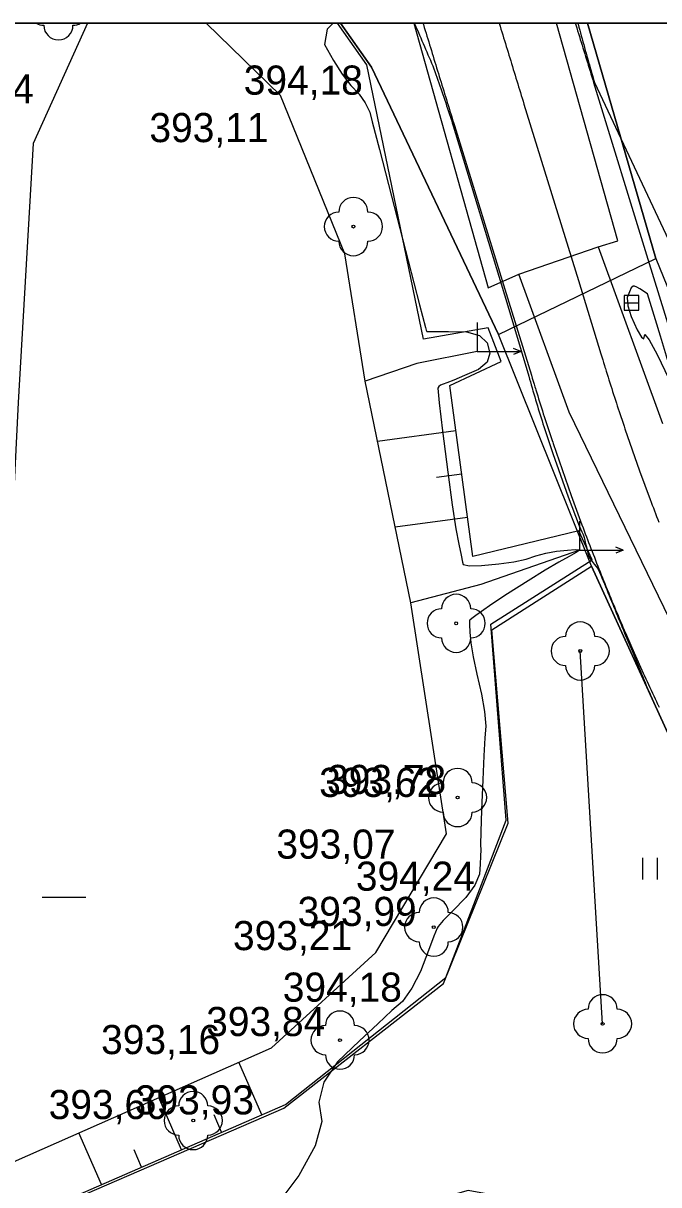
# Model space of a CAD drawing. Extents: x -574342 to -508101, y -1143544 to -1123894.
# Drawn here: x -508495.78 to -508473.95, y -1143155.94 to -1143116.06 of the extents above; entities that cross this region are included whole.
import ezdxf

# ---------------------------------------------------------------- set-up
doc = ezdxf.new("R2010")
doc.units = 0
for name, color, linetype in [('01_PARCELY_NAVRH_PC', 7, 'Continuous'), ('01_PARCELY_NAVRH_VHO', 7, 'Continuous'), ('01_PARCELY_NAVRH_ŽP', 7, 'Continuous'), ('1000', 7, 'Continuous'), ('21', 7, 'Continuous'), ('30', 7, 'Continuous'), ('37', 7, 'Continuous'), ('43', 7, 'Continuous'), ('51', 7, 'Continuous'), ('52', 7, 'Continuous'), ('54', 7, 'Continuous'), ('55', 7, 'Continuous'), ('60', 7, 'Continuous'), ('61', 7, 'Continuous'), ('Level 1', 7, 'Continuous'), ('Level 255', 7, 'Continuous'), ('VRST VEDL', 7, 'Continuous')]:
    doc.layers.add(name, color=color, linetype=linetype)

msp = doc.modelspace()

# ---------------------------------------------------------------- linework, layer by layer
at = {"layer": '01_PARCELY_NAVRH_PC'}
msp.add_line((-508476.398, -1143116.058), (-508484.878, -1143116.058), dxfattribs=at)
for points in [[(-508484.878, -1143116.058), (-508483.82, -1143117.57), (-508479.46, -1143126.74), (-508474.05, -1143124.14), (-508476.398, -1143116.058)], [(-508445.99, -1143206.42), (-508454.33, -1143183.49), (-508456.87, -1143173.84), (-508463.3, -1143163.03), (-508476.26, -1143134.7), (-508479.46, -1143126.74), (-508474.05, -1143124.14), (-508467.92, -1143139.18), (-508459.97, -1143152.33), (-508456.09, -1143158.71), (-508451.57, -1143168.14), (-508437.66, -1143207.58)]]:
    msp.add_lwpolyline(points, dxfattribs=at)
at = {"layer": '01_PARCELY_NAVRH_VHO'}
msp.add_line((-508484.878, -1143116.058), (-508496.906, -1143116.058), dxfattribs=at)
msp.add_lwpolyline([(-508497.89, -1143158.09), (-508486.83, -1143153.3), (-508481.34, -1143149.03), (-508479.12, -1143143.52), (-508479.68, -1143136.88), (-508476.26, -1143134.7), (-508479.46, -1143126.74), (-508483.82, -1143117.57), (-508484.878, -1143116.058)], dxfattribs=at)
at = {"layer": '01_PARCELY_NAVRH_ŽP'}
msp.add_line((-508467.879, -1143116.058), (-508476.398, -1143116.058), dxfattribs=at)
msp.add_lwpolyline([(-508476.398, -1143116.058), (-508474.05, -1143124.14), (-508467.92, -1143139.18), (-508459.97, -1143152.33), (-508456.09, -1143158.71), (-508451.57, -1143168.14), (-508437.66, -1143207.58), (-508425.52, -1143241.92), (-508422.7, -1143249.88), (-508420.04, -1143252.1), (-508417.38, -1143252.95), (-508415.56, -1143252.78), (-508448.24, -1143160.16), (-508453.75, -1143145.01), (-508465.11, -1143123.03), (-508467.879, -1143116.058)], dxfattribs=at)
msp.add_lwpolyline([(-508521.06, -1143176.58), (-508518.2, -1143171.1), (-508515.68, -1143172.08), (-508512.27, -1143171.56), (-508509.12, -1143169.33), (-508497.89, -1143158.09), (-508486.83, -1143153.3), (-508481.34, -1143149.03), (-508479.12, -1143143.52), (-508479.68, -1143136.88), (-508476.26, -1143134.7), (-508463.3, -1143163.03), (-508471.45, -1143157.79), (-508480.5, -1143156.13), (-508491.25, -1143159.19), (-508499.36, -1143164.43), (-508507.52, -1143173.92), (-508509.38, -1143179.27), (-508513.26, -1143177.6)], close=True, dxfattribs=at)
at = {"layer": '1000'}
for points in [[(-508482.347, -1143116.058), (-508482.334, -1143116.087), (-508482.292, -1143116.182), (-508482.25, -1143116.278), (-508482.208, -1143116.373), (-508482.167, -1143116.469), (-508482.125, -1143116.564), (-508482.084, -1143116.66), (-508482.042, -1143116.756), (-508482.001, -1143116.851), (-508481.96, -1143116.947), (-508481.919, -1143117.043), (-508481.878, -1143117.138), (-508481.837, -1143117.234), (-508481.797, -1143117.33), (-508481.756, -1143117.426), (-508481.715, -1143117.522), (-508481.675, -1143117.618), (-508481.639, -1143117.715), (-508481.605, -1143117.813), (-508481.571, -1143117.911), (-508481.537, -1143118.009), (-508481.504, -1143118.107), (-508481.47, -1143118.205), (-508481.436, -1143118.303), (-508481.403, -1143118.401), (-508481.37, -1143118.499), (-508481.336, -1143118.597), (-508481.303, -1143118.695), (-508481.27, -1143118.793), (-508481.237, -1143118.891), (-508481.205, -1143118.99), (-508481.172, -1143119.088), (-508481.139, -1143119.186), (-508481.107, -1143119.285), (-508481.075, -1143119.383), (-508481.042, -1143119.482), (-508481.01, -1143119.58), (-508479.166, -1143125.649)], [(-508482.052, -1143116.058), (-508482.037, -1143116.104), (-508482.007, -1143116.203), (-508481.976, -1143116.302), (-508481.946, -1143116.401), (-508481.915, -1143116.5), (-508481.885, -1143116.599), (-508481.854, -1143116.698), (-508481.824, -1143116.797), (-508481.793, -1143116.896), (-508481.763, -1143116.995), (-508481.732, -1143117.094), (-508481.702, -1143117.192), (-508481.672, -1143117.291), (-508481.641, -1143117.39), (-508481.611, -1143117.489), (-508481.58, -1143117.588), (-508481.55, -1143117.687), (-508481.519, -1143117.786), (-508481.489, -1143117.885), (-508481.458, -1143117.984), (-508481.428, -1143118.083), (-508481.397, -1143118.182), (-508481.367, -1143118.281), (-508481.336, -1143118.38), (-508481.306, -1143118.479), (-508481.275, -1143118.578), (-508481.245, -1143118.677), (-508481.214, -1143118.776), (-508481.184, -1143118.875), (-508481.153, -1143118.974), (-508481.123, -1143119.073), (-508481.092, -1143119.172), (-508481.062, -1143119.271), (-508481.031, -1143119.37), (-508481.001, -1143119.469), (-508480.97, -1143119.568), (-508479.103, -1143125.63)], [(-508476.82, -1143116.058), (-508476.802, -1143116.116), (-508476.771, -1143116.215), (-508476.741, -1143116.314), (-508476.71, -1143116.413), (-508476.68, -1143116.512), (-508476.649, -1143116.611), (-508476.619, -1143116.71), (-508476.588, -1143116.809), (-508476.558, -1143116.908), (-508476.527, -1143117.007), (-508476.497, -1143117.106), (-508476.466, -1143117.205), (-508476.436, -1143117.304), (-508476.405, -1143117.403), (-508476.375, -1143117.502), (-508476.344, -1143117.601), (-508476.314, -1143117.7), (-508476.283, -1143117.799), (-508476.253, -1143117.898), (-508476.222, -1143117.997), (-508476.192, -1143118.096), (-508474.325, -1143124.158)], [(-508476.731, -1143116.058), (-508476.722, -1143116.092), (-508476.694, -1143116.192), (-508476.667, -1143116.292), (-508476.64, -1143116.392), (-508476.613, -1143116.492), (-508476.585, -1143116.592), (-508476.558, -1143116.691), (-508476.53, -1143116.791), (-508476.502, -1143116.891), (-508476.475, -1143116.991), (-508476.447, -1143117.091), (-508476.419, -1143117.19), (-508476.391, -1143117.29), (-508476.362, -1143117.39), (-508476.334, -1143117.489), (-508476.306, -1143117.589), (-508476.277, -1143117.689), (-508476.249, -1143117.788), (-508476.22, -1143117.888), (-508476.192, -1143117.987), (-508476.163, -1143118.087), (-508473.44, -1143123.887)], [(-508474.325, -1143124.158), (-508473.55, -1143126.674)], [(-508479.166, -1143125.649), (-508478.416, -1143128.173), (-508478.388, -1143128.273), (-508478.359, -1143128.373), (-508478.331, -1143128.473), (-508478.302, -1143128.573), (-508478.286, -1143128.63), (-508478.273, -1143128.675), (-508478.243, -1143128.778), (-508478.213, -1143128.881), (-508478.182, -1143128.984), (-508478.152, -1143129.087), (-508478.121, -1143129.19), (-508478.09, -1143129.293), (-508478.058, -1143129.395), (-508478.026, -1143129.498), (-508477.995, -1143129.601), (-508477.962, -1143129.703), (-508477.93, -1143129.806), (-508477.897, -1143129.908), (-508477.864, -1143130.01), (-508477.831, -1143130.112), (-508477.798, -1143130.215), (-508477.764, -1143130.317), (-508477.73, -1143130.419), (-508477.709, -1143130.482), (-508477.696, -1143130.52), (-508477.662, -1143130.622), (-508477.627, -1143130.724), (-508477.593, -1143130.826), (-508477.065, -1143132.312), (-508476.682, -1143133.316), (-508476.638, -1143133.416), (-508476.595, -1143133.515), (-508476.552, -1143133.614), (-508476.513, -1143133.715), (-508476.488, -1143133.822), (-508476.464, -1143133.928), (-508476.439, -1143134.034), (-508476.414, -1143134.14), (-508476.414, -1143134.14), (-508476.388, -1143134.247), (-508476.363, -1143134.353), (-508476.314, -1143134.45), (-508476.242, -1143134.538), (-508476.169, -1143134.626), (-508476.097, -1143134.713), (-508476.035, -1143134.805), (-508475.99, -1143134.903), (-508475.947, -1143135.002), (-508475.905, -1143135.102), (-508475.863, -1143135.201), (-508475.821, -1143135.3), (-508475.821, -1143135.301), (-508475.78, -1143135.401), (-508475.739, -1143135.501), (-508475.698, -1143135.601), (-508475.658, -1143135.701), (-508475.617, -1143135.801), (-508475.579, -1143135.894), (-508475.576, -1143135.901), (-508475.535, -1143136.001), (-508475.494, -1143136.101), (-508475.453, -1143136.201), (-508475.412, -1143136.301), (-508475.371, -1143136.401), (-508475.33, -1143136.501), (-508475.289, -1143136.601), (-508475.247, -1143136.701), (-508475.206, -1143136.801), (-508475.165, -1143136.9), (-508475.124, -1143137), (-508474.837, -1143137.685), (-508474.542, -1143138.392), (-508474.502, -1143138.492), (-508474.461, -1143138.593), (-508474.421, -1143138.693), (-508474.38, -1143138.793), (-508474.339, -1143138.893), (-508474.296, -1143138.992), (-508474.252, -1143139.091), (-508474.208, -1143139.19), (-508474.164, -1143139.289), (-508474.12, -1143139.387), (-508474.082, -1143139.471), (-508474.075, -1143139.486), (-508474.03, -1143139.584), (-508473.985, -1143139.682), (-508473.94, -1143139.78)], [(-508479.103, -1143125.63), (-508478.328, -1143128.146), (-508478.297, -1143128.245), (-508478.267, -1143128.344), (-508478.236, -1143128.444), (-508478.206, -1143128.543), (-508478.188, -1143128.599), (-508478.174, -1143128.644), (-508478.143, -1143128.747), (-508478.111, -1143128.849), (-508478.079, -1143128.951), (-508478.047, -1143129.054), (-508478.015, -1143129.156), (-508477.982, -1143129.258), (-508477.95, -1143129.361), (-508477.917, -1143129.463), (-508477.884, -1143129.565), (-508477.851, -1143129.667), (-508477.818, -1143129.769), (-508477.785, -1143129.871), (-508477.752, -1143129.973), (-508477.718, -1143130.075), (-508477.685, -1143130.177), (-508477.651, -1143130.279), (-508477.617, -1143130.381), (-508477.596, -1143130.444), (-508477.583, -1143130.483), (-508477.549, -1143130.584), (-508477.515, -1143130.686), (-508477.481, -1143130.788), (-508476.961, -1143132.274), (-508476.591, -1143133.282), (-508476.553, -1143133.383), (-508476.514, -1143133.485), (-508476.476, -1143133.586), (-508476.438, -1143133.686), (-508476.399, -1143133.787), (-508476.361, -1143133.888), (-508476.322, -1143133.989), (-508476.283, -1143134.089), (-508476.283, -1143134.09), (-508476.244, -1143134.191), (-508476.205, -1143134.291), (-508476.165, -1143134.392), (-508476.126, -1143134.492), (-508476.086, -1143134.593), (-508476.047, -1143134.693), (-508476.007, -1143134.794), (-508475.967, -1143134.894), (-508475.927, -1143134.994), (-508475.886, -1143135.095), (-508475.846, -1143135.195), (-508475.806, -1143135.294), (-508475.806, -1143135.295), (-508475.765, -1143135.395), (-508475.724, -1143135.495), (-508475.683, -1143135.595), (-508475.642, -1143135.695), (-508475.601, -1143135.795), (-508475.563, -1143135.887), (-508475.56, -1143135.895), (-508475.518, -1143135.994), (-508475.477, -1143136.094), (-508475.435, -1143136.194), (-508475.393, -1143136.293), (-508475.351, -1143136.393), (-508475.309, -1143136.492), (-508475.267, -1143136.592), (-508475.225, -1143136.691), (-508475.182, -1143136.79), (-508475.14, -1143136.89), (-508475.097, -1143136.989), (-508474.8, -1143137.668), (-508474.487, -1143138.367), (-508474.443, -1143138.466), (-508474.398, -1143138.564), (-508474.353, -1143138.662), (-508474.308, -1143138.76), (-508474.263, -1143138.858), (-508474.218, -1143138.956), (-508474.172, -1143139.054), (-508474.127, -1143139.152), (-508474.081, -1143139.25), (-508474.035, -1143139.348), (-508473.996, -1143139.431), (-508473.99, -1143139.445), (-508473.944, -1143139.543)]]:
    msp.add_lwpolyline(points, dxfattribs=at)
at = {"layer": '21'}
for points in [[(-508479.436, -1143116.058), (-508479.435, -1143116.061), (-508479.404, -1143116.16), (-508479.374, -1143116.259), (-508479.343, -1143116.358), (-508479.313, -1143116.457), (-508479.282, -1143116.555), (-508479.252, -1143116.654), (-508479.221, -1143116.753), (-508479.191, -1143116.852), (-508479.16, -1143116.951), (-508479.13, -1143117.05), (-508479.099, -1143117.149), (-508479.069, -1143117.248), (-508479.038, -1143117.347), (-508479.008, -1143117.446), (-508478.977, -1143117.545), (-508478.947, -1143117.644), (-508478.916, -1143117.743), (-508478.886, -1143117.842), (-508478.856, -1143117.941), (-508478.825, -1143118.04), (-508478.795, -1143118.139), (-508478.764, -1143118.238), (-508478.734, -1143118.337), (-508478.703, -1143118.436), (-508478.673, -1143118.535), (-508478.642, -1143118.634), (-508478.612, -1143118.733), (-508478.581, -1143118.832), (-508476.714, -1143124.894)], [(-508476.714, -1143124.894), (-508475.939, -1143127.41), (-508475.908, -1143127.509), (-508475.878, -1143127.609), (-508475.847, -1143127.708), (-508475.816, -1143127.807), (-508475.799, -1143127.863), (-508475.786, -1143127.907), (-508475.755, -1143128.006), (-508475.724, -1143128.106), (-508475.693, -1143128.205), (-508475.662, -1143128.304), (-508475.631, -1143128.403), (-508475.599, -1143128.503), (-508475.568, -1143128.602), (-508475.536, -1143128.701), (-508475.504, -1143128.8), (-508475.472, -1143128.899), (-508475.44, -1143128.998), (-508475.408, -1143129.097), (-508475.376, -1143129.196), (-508475.343, -1143129.295), (-508475.311, -1143129.393), (-508475.278, -1143129.492), (-508475.245, -1143129.591), (-508475.225, -1143129.652), (-508475.212, -1143129.69), (-508475.179, -1143129.788), (-508475.146, -1143129.887), (-508475.113, -1143129.985), (-508474.609, -1143131.427), (-508474.25, -1143132.404), (-508474.213, -1143132.503), (-508474.176, -1143132.601), (-508474.139, -1143132.698), (-508474.102, -1143132.796), (-508474.064, -1143132.894), (-508474.027, -1143132.992), (-508473.989, -1143133.09), (-508473.952, -1143133.187)]]:
    msp.add_lwpolyline(points, dxfattribs=at)
at = {"layer": '30'}
for centre, start, end in [((-508495.07, -1143115.63), 238.8312, 270), ((-508494.57, -1143116.13), 180, 0)]:
    msp.add_arc(centre, 0.5, start, end, dxfattribs=at)
at = {"layer": '37'}
for points in [[(-508482.365, -1143116.058), (-508479.81, -1143125.14), (-508478.76, -1143124.67)], [(-508482.365, -1143116.058), (-508479.81, -1143125.14), (-508478.76, -1143124.67)], [(-508476.03, -1143123.74), (-508475.36, -1143123.53), (-508477.463, -1143116.058)], [(-508476.03, -1143123.74), (-508475.36, -1143123.53), (-508477.463, -1143116.058)], [(-508470.5, -1143142.85), (-508477.03, -1143129.41), (-508478.76, -1143124.67), (-508476.03, -1143123.74), (-508473.82, -1143129.8)], [(-508470.5, -1143142.85), (-508477.03, -1143129.41), (-508478.76, -1143124.67), (-508476.03, -1143123.74), (-508473.82, -1143129.8)]]:
    msp.add_lwpolyline(points, dxfattribs=at)
at = {"layer": '43'}
for p, q in [((-508474.498, -1143145.457), (-508474.498, -1143144.707)), ((-508473.998, -1143145.457), (-508473.998, -1143144.707)), ((-508495.131, -1143146.057), (-508493.631, -1143146.057))]:
    msp.add_line(p, q, dxfattribs=at)
at = {"layer": '51'}
msp.add_line((-508489.496, -1143116.058), (-508493.571, -1143116.058), dxfattribs=at)
msp.add_line((-508489.496, -1143116.058), (-508493.571, -1143116.058), dxfattribs=at)
msp.add_lwpolyline([(-508493.571, -1143116.058), (-508495.44, -1143120.19), (-508495.95, -1143129.08), (-508496.26, -1143135.35), (-508498.94, -1143141.93), (-508503.68, -1143148.5), (-508507.66, -1143152.38), (-508520.2, -1143160.98), (-508521.82, -1143163.95), (-508518.57, -1143168.12), (-508515.5, -1143169.45), (-508512.14, -1143168.95), (-508504.12, -1143160.81), (-508497.6, -1143155.8), (-508487.25, -1143151.23), (-508483.67, -1143147.96), (-508481.24, -1143143.89), (-508482.47, -1143135.96), (-508484.03, -1143128.35), (-508484.73, -1143123.98), (-508486.94, -1143118.54), (-508489.496, -1143116.058)], dxfattribs=at)
msp.add_lwpolyline([(-508493.571, -1143116.058), (-508495.44, -1143120.19), (-508495.95, -1143129.08), (-508496.26, -1143135.35), (-508498.94, -1143141.93), (-508503.68, -1143148.5), (-508507.66, -1143152.38), (-508520.2, -1143160.98), (-508521.82, -1143163.95), (-508518.57, -1143168.12), (-508515.5, -1143169.45), (-508512.14, -1143168.95), (-508504.12, -1143160.81), (-508497.6, -1143155.8), (-508487.25, -1143151.23), (-508483.67, -1143147.96), (-508481.24, -1143143.89), (-508482.47, -1143135.96), (-508484.03, -1143128.35), (-508484.73, -1143123.98), (-508486.94, -1143118.54), (-508489.496, -1143116.058)], dxfattribs=at)
at = {"layer": '52'}
for p, q in [((-508475.14, -1143125.66), (-508474.64, -1143125.66)), ((-508480.19, -1143126.33), (-508480.19, -1143127.33)), ((-508480.19, -1143127.33), (-508478.69, -1143127.33)), ((-508478.69, -1143127.33), (-508478.94, -1143127.23)), ((-508478.69, -1143127.33), (-508478.94, -1143127.43)), ((-508476.68, -1143133.15), (-508476.68, -1143134.15)), ((-508476.68, -1143134.15), (-508475.18, -1143134.15)), ((-508475.18, -1143134.15), (-508475.43, -1143134.05)), ((-508475.18, -1143134.15), (-508475.43, -1143134.25))]:
    msp.add_line(p, q, dxfattribs=at)
msp.add_lwpolyline([(-508475.14, -1143125.91), (-508474.64, -1143125.91), (-508474.64, -1143125.41), (-508475.14, -1143125.41)], close=True, dxfattribs=at)
at = {"layer": '54'}
for centre in [(-508484.44, -1143123.04), (-508480.91, -1143136.66), (-508476.65, -1143137.61), (-508480.86, -1143142.64), (-508481.68, -1143147.09), (-508475.88, -1143150.41), (-508484.9, -1143150.97), (-508489.94, -1143153.73)]:
    msp.add_circle(centre, 0.05, dxfattribs=at)
for centre, start, end in [((-508495.07, -1143115.63), 238.8312, 270), ((-508494.57, -1143116.13), 180, 0), ((-508494.07, -1143115.63), 270, 301.1688), ((-508484.44, -1143122.54), 0, 180), ((-508484.94, -1143123.04), 90, 270), ((-508483.94, -1143123.04), 270, 90), ((-508484.44, -1143123.54), 180, 0), ((-508480.91, -1143136.16), 0, 180), ((-508481.41, -1143136.66), 90, 270), ((-508480.41, -1143136.66), 270, 90), ((-508476.65, -1143137.11), 0, 180), ((-508477.15, -1143137.61), 90, 270), ((-508476.15, -1143137.61), 270, 90), ((-508480.91, -1143137.16), 180, 0), ((-508476.65, -1143138.11), 180, 0), ((-508480.86, -1143142.14), 0, 180), ((-508481.36, -1143142.64), 90, 270), ((-508480.36, -1143142.64), 270, 90), ((-508480.86, -1143143.14), 180, 0), ((-508481.68, -1143146.59), 0, 180), ((-508482.18, -1143147.09), 90, 270), ((-508481.18, -1143147.09), 270, 90), ((-508481.68, -1143147.59), 180, 0), ((-508475.88, -1143149.91), 0, 180), ((-508476.38, -1143150.41), 90, 270), ((-508475.38, -1143150.41), 270, 90), ((-508484.9, -1143150.47), 0, 180), ((-508485.4, -1143150.97), 90, 270), ((-508484.4, -1143150.97), 270, 90), ((-508475.88, -1143150.91), 180, 0), ((-508484.9, -1143151.47), 180, 0), ((-508489.94, -1143153.23), 0, 180), ((-508490.44, -1143153.73), 90, 270), ((-508489.44, -1143153.73), 270, 90), ((-508489.94, -1143154.23), 180, 0)]:
    msp.add_arc(centre, 0.5, start, end, dxfattribs=at)
at = {"layer": '55'}
msp.add_line((-508475.88, -1143150.41), (-508476.65, -1143137.61), dxfattribs=at)
msp.add_line((-508475.88, -1143150.41), (-508476.65, -1143137.61), dxfattribs=at)
at = {"layer": '60'}
for points in [[(-508515.74, -1143172.05), (-508512.28, -1143171.53), (-508508.56, -1143168.5), (-508497.82, -1143157.99), (-508486.77, -1143153.18), (-508481.27, -1143148.82), (-508479.19, -1143143.42), (-508479.72, -1143136.69), (-508476.24, -1143134.48), (-508476.7, -1143133.48), (-508480.34, -1143134.37), (-508481.13, -1143128.49), (-508479.36, -1143127.67), (-508479.81, -1143126.52), (-508482.03, -1143126.91), (-508483.98, -1143117.49), (-508484.986, -1143116.058)], [(-508515.74, -1143172.05), (-508512.28, -1143171.53), (-508508.56, -1143168.5), (-508497.82, -1143157.99), (-508486.77, -1143153.18), (-508481.27, -1143148.82), (-508479.19, -1143143.42), (-508479.72, -1143136.69), (-508476.24, -1143134.48), (-508476.7, -1143133.48), (-508480.34, -1143134.37), (-508481.13, -1143128.49), (-508479.36, -1143127.67), (-508479.81, -1143126.52), (-508482.03, -1143126.91), (-508483.98, -1143117.49), (-508484.986, -1143116.058)], [(-508480.19, -1143127.33), (-508482.26, -1143127.74), (-508484.03, -1143128.35)], [(-508480.19, -1143127.33), (-508482.26, -1143127.74), (-508484.03, -1143128.35)], [(-508476.68, -1143134.15), (-508480.06, -1143135.33), (-508482.47, -1143135.96)], [(-508476.68, -1143134.15), (-508480.06, -1143135.33), (-508482.47, -1143135.96)]]:
    msp.add_lwpolyline(points, dxfattribs=at)
at = {"layer": '61'}
for p, q in [((-508480.92, -1143130.051), (-508483.607, -1143130.412)), ((-508480.92, -1143130.051), (-508483.607, -1143130.412)), ((-508480.721, -1143131.538), (-508481.581, -1143131.653)), ((-508480.721, -1143131.538), (-508481.581, -1143131.653)), ((-508480.521, -1143133.024), (-508483.003, -1143133.358)), ((-508480.521, -1143133.024), (-508483.003, -1143133.358)), ((-508487.589, -1143153.536), (-508488.376, -1143151.727)), ((-508487.589, -1143153.536), (-508488.376, -1143151.727)), ((-508490.34, -1143154.734), (-508491.121, -1143152.939)), ((-508490.34, -1143154.734), (-508491.121, -1143152.939)), ((-508488.964, -1143154.135), (-508489.226, -1143153.535)), ((-508488.964, -1143154.135), (-508489.226, -1143153.535)), ((-508493.09, -1143155.931), (-508493.865, -1143154.151)), ((-508493.09, -1143155.931), (-508493.865, -1143154.151)), ((-508491.715, -1143155.333), (-508491.974, -1143154.737)), ((-508491.715, -1143155.333), (-508491.974, -1143154.737))]:
    msp.add_line(p, q, dxfattribs=at)
msp.add_lwpolyline([(-508482.365, -1143116.058), (-508479.81, -1143125.14), (-508478.76, -1143124.67)], dxfattribs=at)
msp.add_lwpolyline([(-508482.365, -1143116.058), (-508479.81, -1143125.14), (-508478.76, -1143124.67)], dxfattribs=at)
at = {"layer": 'Level 1'}
msp.add_lwpolyline([(-508703.096, -1143116.058), (-508109.096, -1143116.058), (-508109.096, -1143536.058), (-508703.096, -1143536.058)], close=True, dxfattribs=at)
at = {"layer": 'VRST VEDL'}
msp.add_lwpolyline([(-508485.136, -1143116.058), (-508485.337, -1143116.26), (-508485.43, -1143116.787), (-508485.12, -1143117.343), (-508484.82, -1143117.812), (-508484.529, -1143118.194), (-508484.247, -1143118.489), (-508484.03, -1143118.795), (-508483.878, -1143119.111), (-508483.79, -1143119.438), (-508483.541, -1143120.398), (-508483.13, -1143121.991), (-508482.557, -1143124.218), (-508482.17, -1143125.721), (-508481.969, -1143126.499), (-508481.954, -1143126.553), (-508481.94, -1143126.594), (-508481.927, -1143126.622), (-508481.915, -1143126.637), (-508481.895, -1143126.645), (-508481.866, -1143126.646), (-508481.828, -1143126.64), (-508481.597, -1143126.64), (-508481.173, -1143126.645), (-508480.555, -1143126.657), (-508480.112, -1143126.784), (-508479.844, -1143127.027), (-508479.75, -1143127.385), (-508479.849, -1143127.693), (-508480.141, -1143127.95), (-508480.626, -1143128.156), (-508480.99, -1143128.307), (-508481.235, -1143128.403), (-508481.36, -1143128.444), (-508481.451, -1143128.487), (-508481.51, -1143128.533), (-508481.535, -1143128.582), (-508481.491, -1143129.088), (-508481.379, -1143130.051), (-508481.198, -1143131.471), (-508481.044, -1143132.593), (-508480.916, -1143133.417), (-508480.817, -1143133.943), (-508480.742, -1143134.322), (-508480.692, -1143134.555), (-508480.668, -1143134.642), (-508480.452, -1143134.682), (-508480.044, -1143134.675), (-508479.444, -1143134.621), (-508478.934, -1143134.547), (-508478.511, -1143134.453), (-508478.177, -1143134.338), (-508477.828, -1143134.249), (-508477.465, -1143134.185), (-508477.086, -1143134.146), (-508476.829, -1143134.129), (-508476.695, -1143134.132), (-508476.683, -1143134.156), (-508476.794, -1143134.234), (-508477.027, -1143134.367), (-508477.382, -1143134.555), (-508477.854, -1143134.832), (-508478.442, -1143135.198), (-508479.146, -1143135.652), (-508479.68, -1143136.003), (-508480.044, -1143136.249), (-508480.238, -1143136.39), (-508480.372, -1143136.49), (-508480.445, -1143136.548), (-508480.458, -1143136.565), (-508480.455, -1143136.701), (-508480.438, -1143136.958), (-508480.406, -1143137.334), (-508480.329, -1143137.815), (-508480.206, -1143138.402), (-508480.038, -1143139.093), (-508479.935, -1143139.689), (-508479.897, -1143140.19), (-508479.925, -1143140.595), (-508479.958, -1143141.211), (-508479.997, -1143142.037), (-508480.042, -1143143.072), (-508480.068, -1143143.817), (-508480.077, -1143144.27), (-508480.067, -1143144.432), (-508480.069, -1143144.653), (-508480.082, -1143144.934), (-508480.106, -1143145.274), (-508480.273, -1143145.655), (-508480.583, -1143146.077), (-508481.037, -1143146.539), (-508481.351, -1143146.868), (-508481.526, -1143147.063), (-508481.561, -1143147.125), (-508481.674, -1143147.403), (-508481.864, -1143147.898), (-508482.13, -1143148.61), (-508482.428, -1143149.19), (-508482.756, -1143149.639), (-508483.114, -1143149.957), (-508483.605, -1143150.409), (-508484.227, -1143150.995), (-508484.983, -1143151.716), (-508485.45, -1143152.417), (-508485.63, -1143153.099), (-508485.521, -1143153.761), (-508485.749, -1143154.601), (-508486.311, -1143155.618), (-508487.209, -1143156.812)], dxfattribs=at)
msp.add_lwpolyline([(-508474.345, -1143125.352), (-508474.6, -1143125.179), (-508474.703, -1143125.119), (-508474.781, -1143125.087), (-508474.835, -1143125.081), (-508474.896, -1143125.144), (-508474.963, -1143125.274), (-508475.036, -1143125.472), (-508475.017, -1143125.756), (-508474.904, -1143126.127), (-508474.699, -1143126.583), (-508474.551, -1143126.838), (-508474.463, -1143126.891), (-508474.433, -1143126.743), (-508474.28, -1143126.923), (-508474.006, -1143127.431), (-508473.609, -1143128.267), (-508473.424, -1143128.555), (-508473.449, -1143128.295), (-508473.686, -1143127.486), (-508473.891, -1143126.799), (-508474.064, -1143126.235)], close=True, dxfattribs=at)

# ---------------------------------------------------------------- texts
at = {"layer": 'Level 255'}
for s, p in [('394,18', (-508488.205, -1143118.51)), ('393,24', (-508499.505, -1143118.81)), ('393,11', (-508491.445, -1143120.14)), ('393,78', (-508485.345, -1143142.52)), ('393,62', (-508485.615, -1143142.62)), ('393,07', (-508487.085, -1143144.74)), ('394,24', (-508484.355, -1143145.84)), ('393,99', (-508486.355, -1143147.05)), ('393,21', (-508488.575, -1143147.88)), ('394,18', (-508486.865, -1143149.65)), ('393,84', (-508489.495, -1143150.83)), ('393,16', (-508493.105, -1143151.45)), ('393,60', (-508494.905, -1143153.68)), ('393,93', (-508491.945, -1143153.52))]:
    msp.add_text(s, height=1, dxfattribs=at).set_placement(p)

doc.saveas('drawing.dxf')
